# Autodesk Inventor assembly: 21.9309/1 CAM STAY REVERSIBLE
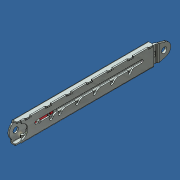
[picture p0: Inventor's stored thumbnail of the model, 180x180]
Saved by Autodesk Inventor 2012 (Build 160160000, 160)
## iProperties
Created: 2016-01
Part Number: 21.9309/1 CAM STAY REVERSIBLE
Document SubType Name: Assembly
Designer: Admin
Description: CAM STAY REVERSIBLE W/0 HRDWR
Translation Standard: STEP AP214IS
FileName: 10 closed position.STEP
PreProcessor: SolidWorks 2015
PostProcessor: Build: 160, Release: 2012 RTM - Date: Tue 03/01/2011
Sent Units: inch
Uncertainty: 1e-05
Author: Admin
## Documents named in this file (5)
- C:\Andys Backup Data\ANDY'S INVENTOR\INVENTOR LIBRARIES\PARTS LIBRARY\HANDLES LOCKS STOPS\SUBCOMPONENTS\21.9309_1 CAM STAY REVERSIBLE NO HARDWARE.iam
- C:\Andys Backup Data\ANDY'S INVENTOR\INVENTOR LIBRARIES\PARTS LIBRARY\HANDLES LOCKS STOPS\SUBCOMPONENTS\21.9309 CAM STAY REVERSIBLE PIN.ipt
- C:\Andys Backup Data\ANDY'S INVENTOR\INVENTOR LIBRARIES\PARTS LIBRARY\HANDLES LOCKS STOPS\SUBCOMPONENTS\21.9309 CAM STAY EXTERIOR.ipt
- C:\Andys Backup Data\ANDY'S INVENTOR\INVENTOR LIBRARIES\PARTS LIBRARY\HANDLES LOCKS STOPS\SUBCOMPONENTS\CAM STAY INTERIOR.ipt
- C:\Andys Backup Data\ANDY'S INVENTOR\INVENTOR LIBRARIES\PARTS LIBRARY\HANDLES LOCKS STOPS\SUBCOMPONENTS\21.9309 CAM STAY CAM.ipt
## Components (4 placed, 4 different names)
1. 21.9309 CAM STAY REVERSIBLE PIN:1 — Flush:1, Mate:1
2. 21.9309 CAM STAY EXTERIOR:1 — Flush:3, Mate:3, Mate:4, Mate:5, Mate:6, Mate:7
3. CAM STAY INTERIOR:1 — Flush:2, Mate:2, Angle:1, Flush:3, Mate:3, Mate:4
4. 21.9309 CAM STAY CAM:1 — Flush:1, Mate:1, Flush:2, Mate:2, Angle:1
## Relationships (11: Mate 7, Flush 3, Angle 1)
- Flush:1: 21.9309 CAM STAY REVERSIBLE PIN:1 ↔ 21.9309 CAM STAY CAM:1
- Mate:1: 21.9309 CAM STAY REVERSIBLE PIN:1 ↔ 21.9309 CAM STAY CAM:1
- Flush:2: CAM STAY INTERIOR:1 ↔ 21.9309 CAM STAY CAM:1
- Mate:2: CAM STAY INTERIOR:1 ↔ 21.9309 CAM STAY CAM:1
- Angle:1: CAM STAY INTERIOR:1 ↔ 21.9309 CAM STAY CAM:1
- Flush:3: 21.9309 CAM STAY EXTERIOR:1 ↔ CAM STAY INTERIOR:1
- Mate:3: 21.9309 CAM STAY EXTERIOR:1 ↔ CAM STAY INTERIOR:1
- Mate:4: 21.9309 CAM STAY EXTERIOR:1 ↔ CAM STAY INTERIOR:1
- Mate:5: 21.9309 CAM STAY EXTERIOR:1
- Mate:6: 21.9309 CAM STAY EXTERIOR:1
- Mate:7: 21.9309 CAM STAY EXTERIOR:1
